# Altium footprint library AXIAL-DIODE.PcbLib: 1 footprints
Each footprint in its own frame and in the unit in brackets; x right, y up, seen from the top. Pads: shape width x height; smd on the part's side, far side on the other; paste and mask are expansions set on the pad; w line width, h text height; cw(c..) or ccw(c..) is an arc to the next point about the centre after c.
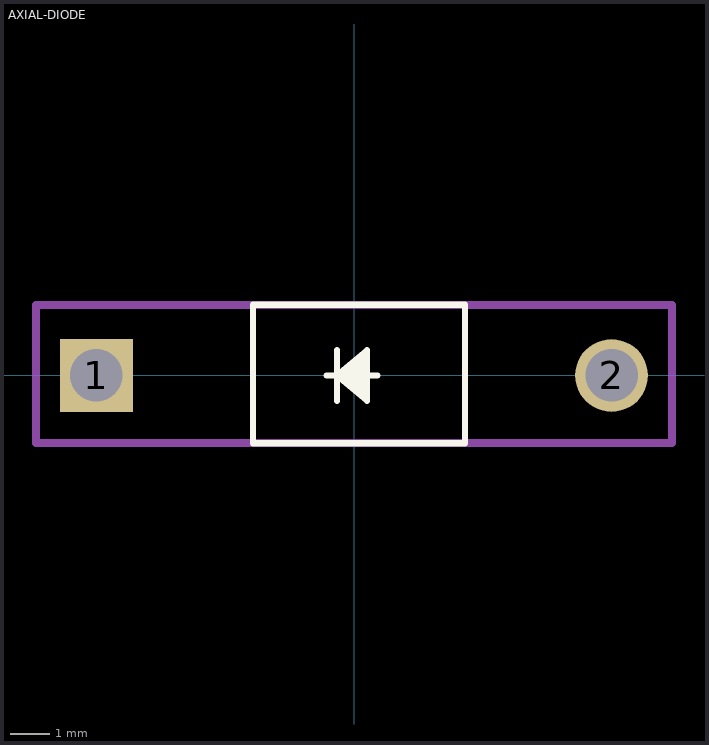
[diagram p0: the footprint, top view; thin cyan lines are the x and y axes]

## AXIAL-DIODE [mil]
pads (2):
  rect 72x72 hole 52: 1(-255,0)
  round 72 hole 52: 2(255,0)
Top Overlay:
  lines w6: -27,0 23,0 ; -17,-25 -17,25 ; 13,-20 -17,0 ; 13,-15 -17,0 ; 13,-10 -17,0 ; 13,-5 -17,0 ; 13,5 -17,0 ; 13,10 -17,0 ; 13,15 -17,0 ; 13,20 -17,0 ; -17,0 13,-25 13,25 -17,0 ; -100,-67.07 -100,70 110,70 110,-67.07 -100,-67.07
Mechanical 15:
  lines w7.87: -315,-66.89 315,-66.89 315,70 -245,70 -315,70 -315,-66.89
3D body "User Library-Diodo 1N5060 (Pitch 500mils).step": height 195.82, standoff -150.47, extent -265.93,-70.6 266.35,71.07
